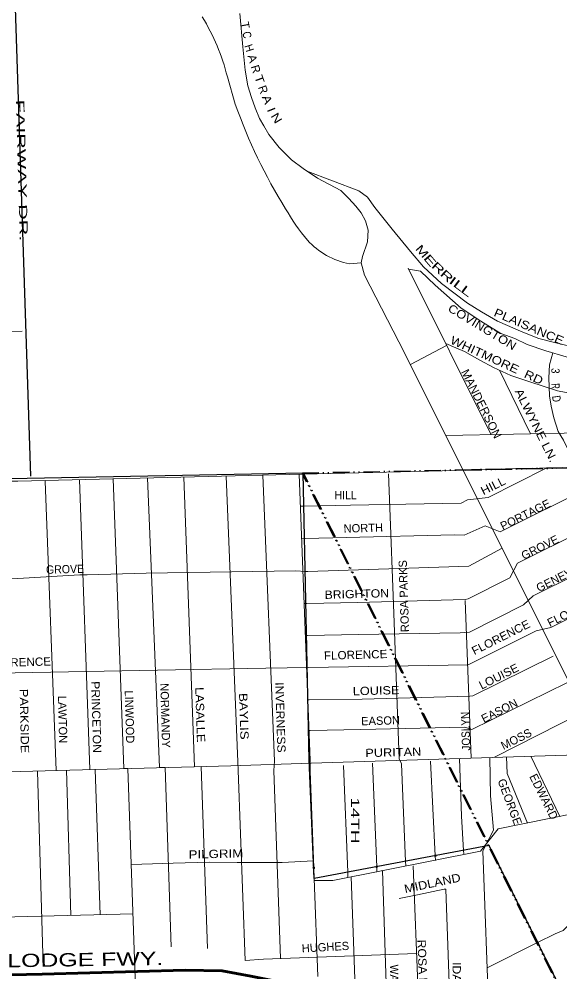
# Model space of a CAD drawing. Extents: x 34705 to 138605, y 34275 to 143551.
# Drawn here: x 77150 to 82043, y 126812 to 135435 of the extents above; entities that cross this region are included whole.
import ezdxf
from ezdxf.enums import TextEntityAlignment as Align

# ---------------------------------------------------------------- set-up
doc = ezdxf.new("R2010")
doc.units = 0
doc.header["$LTSCALE"] = 30
doc.header["$PDMODE"] = 32
doc.header["$PDSIZE"] = 15
doc.linetypes.add('DASH_DOUBLE_DOT', pattern=[9.2, 5, -1.2, 0.3, -1.2, 0.3, -1.2])
for name, color, linetype, lineweight in [('1', 7, 'Continuous', 13), ('11', 7, 'Continuous', 13), ('51', 7, 'Continuous', 35), ('59', 7, 'DASH_DOUBLE_DOT', 106)]:
    doc.layers.add(name, color=color, linetype=linetype, lineweight=lineweight)
doc.layers.add('12', color=7, linetype='Continuous')

msp = doc.modelspace()

# ---------------------------------------------------------------- linework, layer by layer
at = {"layer": '1'}
for p, q in [((79034.43, 134912.37), (79105.8, 134664.64)), ((80140.28, 133220.2), (80243.63, 133228.69)), ((80670.01, 133179.48), (81419.48, 131673.63)), ((77024.21, 132607.9), (77179.34, 132609.29)), ((80689.95, 132309.48), (81017.36, 132481.57)), ((81495.45, 132257.83), (81776.59, 131680.95)), ((81011.87, 131665.28), (84034.97, 131727.21)), ((77387.23, 131252.38), (77485.53, 128634.93)), ((77696.36, 131267.4), (77789.38, 128643.35)), ((79694.82, 131027.39), (79728.82, 131028.17)), ((79706.08, 130732.96), (79736.69, 130733.66)), ((79728.55, 130145.41), (79752.4, 130145.95)), ((81185.97, 130174.22), (81238.79, 128747.67)), ((79739.64, 129855.53), (79760.15, 129855.98)), ((79761.85, 129274.88), (79775.67, 129275.04)), ((79772.54, 128995.58), (79783.14, 128995.82)), ((81778.33, 128764.79), (82041.22, 128219.09)), ((80084.55, 128681.33), (80123.16, 127713.83)), ((80346.94, 128701.02), (80385.36, 127763.44)), ((80871.72, 128720.71), (80915.48, 127863.74)), ((77317.58, 128630.27), (77364.4, 126971.69)), ((77579.98, 128637.54), (77617.09, 127322.94)), ((77837.71, 128644.68), (77884.81, 127328.11)), ((81171.64, 127912.21), (81173.46, 127880.79)), ((81172.65, 127912.4), (81172.66, 127912.19)), ((81357.87, 127947.23), (81358.06, 127947.48)), ((80647.09, 127812.96), (80648.69, 127775.8)), ((80648.1, 127813.15), (80648.11, 127812.94)), ((80915.48, 127863.74), (80917.63, 127821.73)), ((80916.49, 127863.93), (80916.5, 127863.72)), ((79816.31, 127754.42), (79820.07, 127656.48)), ((79816.31, 127754.41), (79816.31, 127754.37)), ((79816.31, 127754.37), (79816.31, 127754.37)), ((80714.28, 127772.53), (80771.48, 126360.91)), ((79820.07, 127656.48), (79854.04, 126770.16)), ((81384.22, 126849.3), (81840.66, 127077.59))]:
    msp.add_line(p, q, dxfattribs=at)
at = {"layer": '1', "lineweight": 25}
for points in [[(83917.87, 122532.88), (84070.94, 122610.5), (81402.19, 127955.82), (79818.93, 127656.27), (79773.35, 128731.82), (79720.91, 131324.36), (77066.34, 131275.68), (76855.3, 136763.37)], [(77080.76, 136532.91), (77095.57, 136091.63), (77254.17, 131298.82)]]:
    msp.add_lwpolyline(points, dxfattribs=at)
at = {"layer": '1'}
for points in [[(79148.15, 135485.96), (79174.39, 135184.12), (79194.07, 134974.14), (79220.31, 134829.78), (79253.11, 134724.79), (79285.91, 134632.92), (79325.26, 134534.49), (79364.62, 134468.88), (79410.54, 134390.13), (79502.38, 134272.02), (79613.89, 134160.47), (79718.85, 134081.73), (79850.04, 133996.42), (80059.95, 133884.87), (80132.11, 133812.69), (80197.71, 133740.51), (80243.63, 133681.45), (80282.98, 133609.27), (80309.22, 133523.97), (80302.66, 133418.98), (80256.75, 133287.74), (80243.63, 133228.69), (80276.42, 133117.13), (80637.21, 132415.02), (86234.97, 121213.34)], [(79747.26, 134060.41), (80223.95, 133881.6), (80302.66, 133822.54), (80368.26, 133730.67), (80525.69, 133533.82), (80689.69, 133330.4), (80807.76, 133192.6), (80971.76, 133041.68), (81207.91, 132864.51), (81332.54, 132785.77), (81476.85, 132700.46), (81706.44, 132602.04), (81850.76, 132542.98), (81981.95, 132510.17), (82145.95, 132470.8), (82329.62, 132437.99), (82441.13, 132431.43)], [(80674.16, 133171.13), (80781.52, 133153.23), (80912.72, 133028.56), (81148.87, 132818.58), (81325.98, 132700.46), (81509.65, 132588.91), (81634.29, 132542.98), (81745.8, 132490.48), (81916.36, 132431.43), (82100.03, 132378.93), (82252.06, 132349.43), (82438.63, 132327.32), (82598.57, 132319.88), (82775.68, 132300.19), (82926.55, 132267.38), (83064.31, 132228.01), (83123.35, 132208.32), (83326.7, 132142.71), (83464.45, 132083.65), (83582.53, 132024.59), (84016.92, 131763.87)], [(81009.47, 132498.69), (81101.31, 132459.32), (81180.02, 132426.51), (81317.78, 132347.77), (81442.41, 132282.15), (81599.85, 132209.97), (81770.4, 132150.91), (81901.59, 132111.54), (82019.67, 132072.17), (82227.19, 132032.89), (82419.81, 132013.11), (82708.44, 131993.43), (83049.55, 131914.69)], [(81979.6, 132413.35), (81949.15, 132306.75), (81942.59, 132188.64), (81949.15, 132024.59), (81962.27, 131932.73), (81988.51, 131827.74), (82027.87, 131703.06), (82073.79, 131624.32), (82716.64, 130325.07), (82716.64, 130325.07), (85912.86, 123919.09), (85958.78, 123794.41), (86385.16, 122947.93), (86444.2, 122862.63), (87053.1, 121625.65)], [(79721.13, 131315.9), (81105.26, 131349.05), (81242.43, 131359.6), (84006.84, 131412.38), (84265.35, 131412.38), (85051.41, 131438.76), (87062.73, 131528.48), (87263.2, 131502.09), (88576.82, 131560.14), (88624.3, 131560.14), (89151.86, 131581.25), (90043.44, 131623.47)], [(79728.82, 131028.17), (80147.75, 131037.69), (81150.11, 131053.52), (81208.14, 131085.18), (81392.79, 131106.29), (81919.29, 131372.52)], [(79736.69, 130733.66), (80110.82, 130742.16), (81086.8, 130768.54), (81176.49, 130763.27), (81366.41, 130847.7), (81503.57, 130794.93), (82318.65, 131201.28), (82674.38, 131386.94)], [(79752.4, 130145.95), (80211.05, 130156.38), (81187.04, 130182.76), (81213.42, 130188.04), (81590.62, 130378.02), (81659.2, 130509.95), (83447.51, 131401.7)], [(79760.15, 129855.98), (80221.61, 129866.12), (81139.56, 129881.95), (81223.97, 129887.23), (81711.96, 130135.27), (81801.64, 130214.43), (84194.57, 131403.24)], [(68722.14, 131123.45), (70126.76, 131153.79), (71255.74, 131185.45), (73789.34, 131211.84), (74132.25, 131201.28), (74670.36, 131206.56), (76996.9, 131254.06), (77139.34, 131254.06), (79721.13, 131315.9)], [(77999.84, 131274.67), (78097.13, 128651.87), (78133.86, 128652.89), (78225.74, 126065.35), (78363.95, 125871.78), (78391.6, 124922.4), (80465.18, 120783.71)], [(78312.83, 131282.16), (78420.32, 128660.83), (78472.55, 128662.28), (78525.04, 127038.96)], [(78640.35, 131290.01), (78736.77, 128669.6), (78796.46, 128671.25), (78854.49, 127024.93)], [(79023.68, 131299.19), (79128.74, 128713.01), (79133.35, 128634.66), (79194.79, 126914.32)], [(79356.11, 131307.15), (79461.38, 128720.71), (79454.82, 128635.4), (79515.23, 126933.52)], [(79683.81, 131315), (79782.8, 128727.27), (79782.8, 128628.84), (79816.31, 127754.42)], [(80491.25, 131319.2), (80504.37, 131010.79), (80537.17, 130138.07), (80589.65, 128740.39), (80609.33, 128694.46), (80647.09, 127812.96)], [(79767.88, 129566.7), (81213.42, 129591.7), (81828.02, 129897.79), (81959.91, 129929.45), (84339.52, 131109.01)], [(79744.62, 130436.93), (79762.63, 130436.07), (80585.62, 130462.46), (81218.69, 130483.57), (81520.38, 130647.7)], [(81452.18, 128754.44), (82234.24, 129153.69), (82244.79, 129280.34), (84649.24, 130480.3)], [(76099.64, 130362.02), (77139.34, 130372.74), (77698.55, 130404.41), (77767.14, 130404.41), (78299.97, 130420.24), (79651.84, 130441.35), (79744.62, 130436.93)], [(79790.99, 128701.73), (82392.51, 128784.27), (82524.4, 128720.95), (84930.89, 129908.6)], [(79775.67, 129275.04), (80253.26, 129280.34), (81229.24, 129306.73), (81255.62, 129312), (81981.01, 129670.86)], [(81356.85, 127947.25), (81483.53, 128106.04), (82643.94, 128341.28), (82682.49, 128460.83), (85061.7, 129643.06)], [(75806.66, 129506.55), (76105.32, 129517.82), (76147.53, 129496.71), (77114.28, 129517.82), (78401.52, 129544.21), (79382.78, 129560.04), (79767.88, 129566.7)], [(79783.14, 128995.82), (80242.71, 129005.92), (81181.76, 129027.03), (81245.07, 129005.92), (82104.99, 129428.11)], [(81840.66, 127077.59), (82000.13, 127157.35), (82073.37, 127188.21), (82135.06, 127249.91), (82177.46, 127327.04), (82192.89, 127411.88), (82189.03, 127558.42), (82196.74, 127670.26), (82219.87, 127743.53), (82277.7, 127820.66), (82763.45, 128113.75), (82825.13, 128187.02), (85196.59, 129369.26)], [(81133.44, 128744.32), (81153.78, 128222.01), (81171.64, 127912.21)], [(81409.23, 128753.07), (81416.17, 128405.74), (81442.41, 128094.06), (81367.54, 127949.27)], [(81558.79, 128757.82), (81567.05, 128609.15), (81749.29, 128159.91)], [(50901.75, 127912.29), (51076.59, 127951.78), (53429.51, 128025.66), (53735.5, 128025.66), (58802.7, 128162.87), (59905.3, 128215.65), (61846.72, 128284.25), (63556.01, 128358.13), (63587.66, 128358.13), (64447.59, 128389.8), (65614.81, 128410.91), (67682.84, 128463.68), (68864.58, 128479.51), (72639.26, 128541.52), (73551.93, 128552.07), (74601.78, 128562.63), (77161.76, 128625.95), (79066.25, 128678.73), (79790.99, 128701.73)], [(79820.72, 127639.41), (79989.65, 127639.41), (81323.55, 127905.5), (81356.85, 127947.25)], [(81367.54, 127949.27), (81344.02, 127903.76), (81403.05, 126355.16), (81977.74, 125230.49)], [(78166.71, 127785.41), (78451.44, 127793.67), (78543.96, 127797.52), (78871.65, 127805.24), (79122.24, 127801.38), (79199.34, 127801.38), (79461.49, 127801.38), (79530.89, 127801.38), (79813.9, 127817.33)], [(80123.16, 127713.83), (80125.06, 127666.42), (80155.29, 127672.45), (80189.36, 126666.29)], [(80385.36, 127763.44), (80387.2, 127718.71), (80438.05, 127728.86), (80476.34, 126519.27)], [(80589.65, 127477.24), (80753.64, 127510.05), (80996.35, 127562.55), (81009.47, 127562.55), (81054.14, 126372.69)], [(69148.29, 127178.22), (69250.1, 127182.43), (71922.7, 127220.99), (73322.13, 127224.85), (73414.65, 127217.13), (74621.33, 127224.85), (74757.22, 127255.7), (75442.47, 127269.19), (78182.1, 127336.91)], [(79194.79, 126914.32), (79362.22, 126927.9), (80746.45, 126978.75)]]:
    msp.add_lwpolyline(points, dxfattribs=at)
for centre, radius, start, end in [((77128.44, 134433.06), 1965.33, 14.13504, 31.32209), ((83765.7, 136322.61), 4946.1, 199.59922, 211.7743), ((81067.2, 134550.98), 1720.14, 208.92691, 220.50834), ((80269.65, 133897.68), 689.72, 222.26306, 259.18955)]:
    msp.add_arc(centre, radius, start, end, dxfattribs=at)
for p in [(80915.48, 127863.74), (79816.31, 127754.37), (80385.36, 127763.44), (81840.66, 127077.59)]:
    msp.add_point(p, dxfattribs=at)
at = {"layer": '51', "lineweight": 60}
msp.add_lwpolyline([(69647.16, 126779.47), (69954.82, 126695.54), (72939.31, 126697.51), (77358.19, 126791.56), (78651.41, 126828.44), (78987.04, 126821.44), (79245.75, 126772.48), (79504.46, 126723.52), (79735.21, 126667.56), (80049.86, 126569.64), (80371.5, 126415.76), (80735.1, 126156.96), (81049.75, 125919.15), (81399.36, 125506.47), (81783.93, 125128.77), (82081.1, 124959.16), (82297.86, 124756.32), (82661.45, 124455.56), (83178.15, 123900.57), (83909.27, 122531.62)], dxfattribs=at)
at = {"layer": '59', "lineweight": 35}
msp.add_line((82350.59, 126057.29), (79725.38, 131315.41), dxfattribs=at)
for points in [[(92674.01, 124470.72), (85052.76, 120629.83), (79713.12, 131324.76), (84006.84, 131412.38), (85051.41, 131438.76), (87061.1, 131528.41), (87260.49, 131502.45), (88419.69, 131551.9), (91983.3, 125629.39)], [(79713.12, 131324.76), (84006.84, 131412.38), (85051.41, 131438.76), (86415.72, 131499.62)], [(81185.94, 131354.26), (84014.62, 131411.98), (84014.65, 131411.98)], [(92674.01, 124470.72), (85052.76, 120629.83), (79713.12, 131324.76)]]:
    msp.add_lwpolyline(points, dxfattribs=at)

# ---------------------------------------------------------------- texts
at = {"layer": '11'}
for s, height, rotation, width, p in [('T', 75, 280.302, 1.05, (79158.37, 135373.58)), ('C', 75, 280.302, 0.85, (79175.97, 135285.34)), ('H', 75, 287.349, 0.9, (79196.26, 135162.04)), ('A', 75, 287.349, 1.1, (79226.09, 135066.58)), ('T', 75, 289.648, 1.25, (79289.29, 134878.49)), ('A', 75, 291.79, 1.2, (79359.98, 134692.93)), ('FAIRWAY DR.', 75, 271.551, 1.95, (77138.96, 134063.62)), ('I', 75, 291.79, 1.25, (79397.09, 134600.08)), ('N', 75, 300.96, 1.25, (79446.94, 134519.47)), ('M', 75, 310.591, 1.4, (80767.86, 133309.32)), ('E', 75, 310.591, 1.65, (80839, 133226.3)), ('R', 75, 317.378, 1.6, (80916.02, 133154.09)), ('R', 75, 317.378, 1.6, (80994.5, 133081.87)), ('I', 75, 323.121, 1.75, (81051.3, 133037.45)), ('L', 75, 323.121, 1.8, (81108.77, 132994.33)), ('L', 75, 323.121, 1.8, (81176.96, 132943.17)), ('COVINGTON', 75, 328.728, 1.15, (81320.63, 132616.01)), ('PLAISANCE', 75, 336.796, 1.2, (81748.17, 132618.16)), ('WHITMORE  RD', 75, 335.37, 1.2, (81456.47, 132312.82)), ('MANDERSON', 75, 296.545, 1.05, (81298.64, 131936.67)), ('3', 75, 266.821, 0.85, (81965.12, 132254)), ('R', 75, 272.29, 0.7, (81965.98, 132112.46)), ('ALWYNE LN.', 75, 296.545, 1.2, (81794.24, 131740.76)), ('D', 75, 278.128, 0.8, (81975.06, 131994.04)), ('GROVE', 75, 1.555, 0.95, (77566.89, 130419.36)), ('BRIGHTON', 75, 1.555, 1.1, (80206.49, 130195.78)), ('FLORENCE', 75, 1.555, 1.05, (80195.64, 129644.85)), ('FLORENCE', 75, 1.555, 1.05, (77152.99, 129577.66)), ('PRINCETON', 75, 271.557, 1.1, (77811.32, 129117.74)), ('PARKSIDE', 75, 271.111, 1.15, (77160.99, 129081.66)), ('LASALLE', 75, 271.785, 1.15, (78751.76, 129138.4)), ('INVERNESS', 75, 271.785, 1.1, (79477.35, 129114.29)), ('LOUISE', 75, 1.555, 1.15, (80380.97, 129320.69)), ('BAYLIS', 75, 271.784, 1.2, (79146.41, 129124.27)), ('PURITAN', 75, 1.555, 1.15, (80536.41, 128762.45)), ('14TH', 75, 270, 1.7, (80152.82, 128183.16)), ('PILGRIM', 75, 1.453, 1.2, (78931.91, 127843.14)), ('MIDLAND', 75, 11.907, 1.15, (80896.78, 127578.78)), ('ROSA PARKS', 75, 272.366, 1.1, (80768, 126744.5)), ('LODGE FWY.', 120, 0.885, 1.4, (77749.63, 126864.67)), ('WABASH', 75, 270, 0.95, (80506.7, 126673.02)), ('IDAHO', 75, 270, 1.1, (81071.67, 126726.85))]:
    msp.add_text(s, height=height, rotation=rotation, dxfattribs=dict(at, width=width)).set_placement(p, align=Align.CENTER)
for s, rotation, p in [('R', 287.349, (79255.91, 134971.15)), ('R', 289.648, (79322.91, 134784.33)), ('NORTH', 1.555, (80265.16, 130791.87)), ('LINWOOD', 271.558, (78112.41, 129119.36)), ('NORMANDY', 271.556, (78435.43, 129131.09)), ('LAWTON', 271.557, (77506.89, 129095.86)), ('EASON', 1.555, (80421.31, 129048.71)), ('HUGHES', 3.234, (79923.41, 126999.95))]:
    msp.add_text(s, height=75, rotation=rotation, dxfattribs=at).set_placement(p, align=Align.CENTER)
at = {"layer": '12'}
for s, rotation, width, p in [('HILL', 26.462, 1.1, (81454.83, 131177.87)), ('FLORENCE', 26.464, 1.05, (82208.06, 130060.34))]:
    msp.add_text(s, height=75, rotation=rotation, dxfattribs=dict(at, width=width)).set_placement(p, align=Align.CENTER)
at = {"layer": '12', "width": 0.95}
msp.add_text('HILL', height=75, dxfattribs=at).set_placement((80003.7, 131089.97))
at = {"layer": '12'}
for s, rotation, p in [('PORTAGE', 26.464, (81746.13, 130916.57)), ('GROVE', 26.464, (81878.32, 130620.73)), ('GENEVA', 26.465, (82038.89, 130341.17)), ('EDWARD', 296.4, (81863.12, 128381.87)), ('GEORGE', 290.66, (81554.84, 128337.44))]:
    msp.add_text(s, height=75, rotation=rotation, dxfattribs=at).set_placement(p, align=Align.CENTER)
for s, rotation, p in [('ROSA PARKS', 91.829, (80678.39, 129888.21)), ('EASON', 26.683, (81355.55, 129063.67)), ('MOSS', 26.684, (81533.05, 128819.52))]:
    msp.add_text(s, height=75, rotation=rotation, dxfattribs=at).set_placement(p)
for s, rotation, width, p in [('FLORENCE', 26.685, 1.05, (81268.44, 129678)), ('LOUISE', 26.684, 1.05, (81334.1, 129366.42)), ('JOSLYN', 91.823, 0.9, (81232.1, 128816.59))]:
    msp.add_text(s, height=75, rotation=rotation, dxfattribs=dict(at, width=width)).set_placement(p)

doc.saveas('drawing.dxf')
